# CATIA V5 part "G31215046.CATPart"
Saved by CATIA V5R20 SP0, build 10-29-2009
Part number: G31215046
Revision: 6
Definition: design
Nomenclature: G31215046
Source: made
Description: NOT SPECIFIED
Bounding box of the stored display mesh (mm): x -6 to 46, y -12.31 to 12.31, z -12.5 to 12.5
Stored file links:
  C:\Users\Raffaele\Desktop\3D X SITO CF\BOLEX\23-BUSH REF 312\G31215046.CATPart

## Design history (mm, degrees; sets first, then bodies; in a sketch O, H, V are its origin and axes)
Body1 "MANIFOLD_SOLID_BREP #10235" (main body)
  Solid1: solid without history
Body2 "MANIFOLD_SOLID_BREP #10378"
  Solid2: solid without history
Body3 "MANIFOLD_SOLID_BREP #10521"
  Solid3: solid without history
Body4 "MANIFOLD_SOLID_BREP #10664"
  Solid4: solid without history
Body5 "MANIFOLD_SOLID_BREP #10807"
  Solid5: solid without history
Body6 "MANIFOLD_SOLID_BREP #10952"
  Solid6: solid without history
Body7 "MANIFOLD_SOLID_BREP #11097"
  Solid7: solid without history
Body8 "MANIFOLD_SOLID_BREP #11242"
  Solid8: solid without history
Body9 "MANIFOLD_SOLID_BREP #11387"
  Solid9: solid without history
Body10 "MANIFOLD_SOLID_BREP #11532"
  Solid10: solid without history
Body11 "MANIFOLD_SOLID_BREP #11677"
  Solid11: solid without history
Body12 "MANIFOLD_SOLID_BREP #11822"
  Solid12: solid without history
Body13 "MANIFOLD_SOLID_BREP #11967"
  Solid13: solid without history
Body14 "MANIFOLD_SOLID_BREP #12112"
  Solid14: solid without history
Body15 "MANIFOLD_SOLID_BREP #12257"
  Solid15: solid without history
Body16 "MANIFOLD_SOLID_BREP #12402"
  Solid16: solid without history
Body17 "MANIFOLD_SOLID_BREP #12547"
  Solid17: solid without history
Body18 "MANIFOLD_SOLID_BREP #12692"
  Solid18: solid without history
Body19 "MANIFOLD_SOLID_BREP #12837"
  Solid19: solid without history
Body20 "MANIFOLD_SOLID_BREP #12982"
  Solid20: solid without history
Body21 "MANIFOLD_SOLID_BREP #13127"
  Solid21: solid without history
Body22 "MANIFOLD_SOLID_BREP #13272"
  Solid22: solid without history
Body23 "MANIFOLD_SOLID_BREP #13417"
  Solid23: solid without history
Body24 "MANIFOLD_SOLID_BREP #13562"
  Solid24: solid without history
Body25 "MANIFOLD_SOLID_BREP #13707"
  Solid25: solid without history
Body26 "MANIFOLD_SOLID_BREP #13852"
  Solid26: solid without history
Body27 "MANIFOLD_SOLID_BREP #13997"
  Solid27: solid without history
Body28 "MANIFOLD_SOLID_BREP #14142"
  Solid28: solid without history
Body29 "MANIFOLD_SOLID_BREP #14287"
  Solid29: solid without history
Body30 "MANIFOLD_SOLID_BREP #14432"
  Solid30: solid without history
Body31 "MANIFOLD_SOLID_BREP #14577"
  Solid31: solid without history
Body32 "MANIFOLD_SOLID_BREP #14720"
  Solid32: solid without history
Body33 "MANIFOLD_SOLID_BREP #14863"
  Solid33: solid without history
Body34 "MANIFOLD_SOLID_BREP #15008"
  Solid34: solid without history
Body35 "MANIFOLD_SOLID_BREP #15153"
  Solid35: solid without history
Body36 "MANIFOLD_SOLID_BREP #15298"
  Solid36: solid without history
Body37 "MANIFOLD_SOLID_BREP #15443"
  Solid37: solid without history
Body38 "MANIFOLD_SOLID_BREP #15588"
  Solid38: solid without history
Body39 "MANIFOLD_SOLID_BREP #15733"
  Solid39: solid without history
Body40 "MANIFOLD_SOLID_BREP #15878"
  Solid40: solid without history
Body41 "MANIFOLD_SOLID_BREP #16023"
  Solid41: solid without history
Body42 "MANIFOLD_SOLID_BREP #16168"
  Solid42: solid without history
Body43 "MANIFOLD_SOLID_BREP #16313"
  Solid43: solid without history
Body44 "MANIFOLD_SOLID_BREP #16458"
  Solid44: solid without history
Body45 "MANIFOLD_SOLID_BREP #16603"
  Solid45: solid without history
Body46 "MANIFOLD_SOLID_BREP #16748"
  Solid46: solid without history
Body47 "MANIFOLD_SOLID_BREP #16893"
  Solid47: solid without history
Body48 "MANIFOLD_SOLID_BREP #17038"
  Solid48: solid without history
Body49 "MANIFOLD_SOLID_BREP #17183"
  Solid49: solid without history
Body50 "MANIFOLD_SOLID_BREP #17328"
  Solid50: solid without history
Body51 "MANIFOLD_SOLID_BREP #17473"
  Solid51: solid without history
Body52 "MANIFOLD_SOLID_BREP #17618"
  Solid52: solid without history
Body53 "MANIFOLD_SOLID_BREP #17763"
  Solid53: solid without history
Body54 "MANIFOLD_SOLID_BREP #17908"
  Solid54: solid without history
Body55 "MANIFOLD_SOLID_BREP #18053"
  Solid55: solid without history
Body56 "MANIFOLD_SOLID_BREP #18196"
  Solid56: solid without history
Body57 "MANIFOLD_SOLID_BREP #18339"
  Solid57: solid without history
Body58 "MANIFOLD_SOLID_BREP #18484"
  Solid58: solid without history
Body59 "MANIFOLD_SOLID_BREP #18629"
  Solid59: solid without history
Body60 "MANIFOLD_SOLID_BREP #18774"
  Solid60: solid without history
Body61 "MANIFOLD_SOLID_BREP #18919"
  Solid61: solid without history
Body62 "MANIFOLD_SOLID_BREP #19064"
  Solid62: solid without history
Body63 "MANIFOLD_SOLID_BREP #19209"
  Solid63: solid without history
Body64 "MANIFOLD_SOLID_BREP #19352"
  Solid64: solid without history
Body65 "MANIFOLD_SOLID_BREP #19495"
  Solid65: solid without history
Body66 "MANIFOLD_SOLID_BREP #19640"
  Solid66: solid without history
Body67 "MANIFOLD_SOLID_BREP #19785"
  Solid67: solid without history
Body68 "MANIFOLD_SOLID_BREP #19930"
  Solid68: solid without history
Body69 "MANIFOLD_SOLID_BREP #20075"
  Solid69: solid without history
Body70 "MANIFOLD_SOLID_BREP #20220"
  Solid70: solid without history
Body71 "MANIFOLD_SOLID_BREP #20365"
  Solid71: solid without history
Body72 "MANIFOLD_SOLID_BREP #20510"
  Solid72: solid without history
Body73 "MANIFOLD_SOLID_BREP #20655"
  Solid73: solid without history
